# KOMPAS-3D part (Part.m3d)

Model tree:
1. Plane XY
2. Plane ZX
3. Plane ZY
4. X Axis
5. Y Axis
6. Z Axis
7. Origin
8. Sketch:1
9. Extrude:1
     Wall Thickness 1 = 1; Wall Thickness 2 = 1; Distance 1 = 30; Distance 2 = 10
10. Sketch:2  (labels: Extrude:2)
     Wall Thickness 1 = 1; Wall Thickness 2 = 1; Distance 1 = 30; Distance 2 = 10
11. Sketch:3  (labels: Cut-Extrude:1)
     Wall Thickness 1 = 1; Wall Thickness 2 = 1; Distance 2 = 10; Distance 1 = 6
12. Sketch:4  (labels: Extrude:3)
     Wall Thickness 1 = 1; Wall Thickness 2 = 1; Distance 1 = 30; Distance 2 = 10
13. Chamfer:1
     Slope = 45; Length 1 = 1; Length 2 = 1

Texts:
  Steel DIN 17102
  Three Point Plane
  Plane at Angle
  Line and Point Plane
  Axis through Two Vertices
  Axis of Feature
  Axis of Conical Surface
  Axis through Edge
  Trim by Surface
  Trim by Sketch
  Feature with No History
  Intersection Axis of Two Planes
  Two Line Plane
  Line and Face Plane
  Bend by line
  Hole in sheet body
  Cut in sheet body
  Point in CM
  Linear Dimension from Line to Point
  Surface Finish Symbol
  Geometric Tolerance Symbol
  Bend by sketch
  Arc of Circle
  Junction of curves
  Array by nodes of sketch
  Leader #1
  Leader #2
  Leader #3
  Shape Deviations and Datum
  Node point number
  Mark of coordination axis
  Node point designation
  Mark/Reference designation with leader
  Mark/reference designation on line
  Mark/Reference designation without leader
  Hexagonal bolt D10
  Hexagonal bolt D12
  Cylider headl bolt D10
  Cylider headl bolt D12
  Hexagon?0:1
